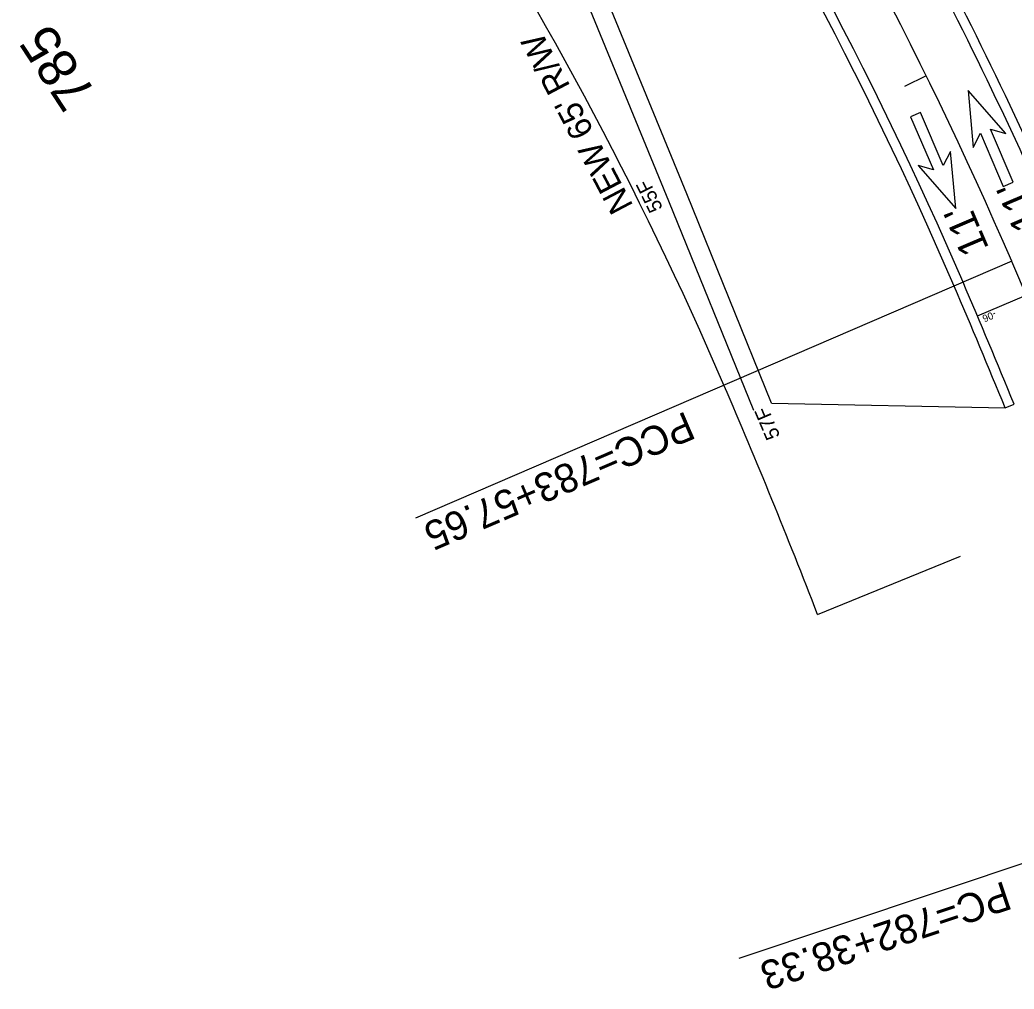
# Model space of a CAD drawing. Extents: x 1551641 to 1624343, y 1119533 to 1136600.
# Drawn here: x 1552695 to 1552901.3, y 1133721.6 to 1133922.6 of the extents above; entities that cross this region are included whole.
import ezdxf

# ---------------------------------------------------------------- set-up
doc = ezdxf.new("R2010")
doc.units = 0
for name, color, linetype in [('RD_HC_Cl', 7, 'Continuous'), ('RD_HC_CL_Rel', 7, 'Continuous'), ('RD_HC_Data', 7, 'Continuous'), ('RD_HC_Data_Tic', 7, 'Continuous'), ('RD_HC_TX_Sta50', 7, 'Continuous'), ('RD_PD_ALT1_TX', 7, 'Continuous'), ('RD_PD_CstnLmt', 7, 'Continuous'), ('RD_PD_CstnLmt_TX', 7, 'Continuous'), ('RD_PD_DR_ErosCtrl', 7, 'Continuous'), ('RD_PD_Final_TrvlWay', 7, 'Continuous'), ('RD_PD_Final_TX', 7, 'Continuous'), ('RD_PD_PaveShd', 7, 'Continuous'), ('RD_PD_RW', 7, 'Continuous')]:
    doc.layers.add(name, color=color, linetype=linetype)

msp = doc.modelspace()

# ---------------------------------------------------------------- linework, layer by layer
at = {"layer": 'RD_HC_Cl'}
msp.add_arc((1551585.14, 1133306.13), 1432.4, 18.5195, 23.29239, dxfattribs=at)
at = {"layer": 'RD_HC_CL_Rel'}
msp.add_arc((1552135.69, 1133543.15), 833, 23.29239, 33.23375, dxfattribs=at)
at = {"layer": 'RD_HC_Data'}
for p, q in [((1552900.8, 1133872.54), (1552777.09, 1133819.28)), ((1552943.36, 1133761.1), (1552844.19, 1133727.88))]:
    msp.add_line(p, q, dxfattribs=at)
at = {"layer": 'RD_HC_Data_Tic'}
msp.add_line((1552883.07, 1133911), (1552878.58, 1133908.79), dxfattribs=at)
at = {"layer": 'RD_PD_ALT1_TX'}
msp.add_line((1552893.68, 1133861.21), (1552903.8, 1133865.5), dxfattribs=at)
at = {"layer": 'RD_PD_CstnLmt'}
for p, q in [((1552833.37, 1133886.53), (1552815.52, 1133930.05)), ((1552850.98, 1133843.1), (1552833.37, 1133886.53)), ((1552850.98, 1133843.1), (1552899.45, 1133842.13))]:
    msp.add_line(p, q, dxfattribs=at)
at = {"layer": 'RD_PD_DR_ErosCtrl'}
for p, q in [((1552829.66, 1133885.02), (1552811.89, 1133928.36)), ((1552847.27, 1133841.59), (1552829.66, 1133885.02))]:
    msp.add_line(p, q, dxfattribs=at)
at = {"layer": 'RD_PD_Final_TrvlWay'}
for centre, radius, start, end in [((1552135.69, 1133543.15), 844, 23.29239, 33.23375), ((1552135.69, 1133543.15), 822, 23.29239, 33.23375), ((1551585.14, 1133306.13), 1421.4, 22.1864, 23.29239)]:
    msp.add_arc(centre, radius, start, end, dxfattribs=at)
at = {"layer": 'RD_PD_Final_TX'}
for p, q in [((1552899.58, 1133899.06), (1552891.78, 1133907.96)), ((1552891.78, 1133907.96), (1552892.82, 1133896.17)), ((1552881.9, 1133903.42), (1552879.83, 1133902.54)), ((1552886.61, 1133892.39), (1552881.9, 1133903.42)), ((1552879.83, 1133902.54), (1552884.55, 1133891.5)), ((1552892.82, 1133896.17), (1552894.34, 1133899.1)), ((1552894.34, 1133899.1), (1552899.06, 1133888.07)), ((1552901.13, 1133888.95), (1552896.41, 1133899.99)), ((1552896.41, 1133899.99), (1552899.58, 1133899.06)), ((1552888.13, 1133895.32), (1552886.61, 1133892.39)), ((1552889.18, 1133883.53), (1552888.13, 1133895.32)), ((1552881.38, 1133892.43), (1552889.18, 1133883.53)), ((1552884.55, 1133891.5), (1552881.38, 1133892.43)), ((1552899.06, 1133888.07), (1552901.13, 1133888.95))]:
    msp.add_line(p, q, dxfattribs=at)
at = {"layer": 'RD_PD_PaveShd'}
msp.add_line((1552899.45, 1133842.13), (1552901.3, 1133842.88), dxfattribs=at)
for centre, radius, start, end in [((1552135.69, 1133543.15), 846, 23.29239, 33.23375), ((1552135.69, 1133543.15), 820, 23.29239, 33.23375), ((1551585.14, 1133306.13), 1419.4, 22.1864, 23.29239)]:
    msp.add_arc(centre, radius, start, end, dxfattribs=at)
at = {"layer": 'RD_PD_RW'}
msp.add_line((1552860.53, 1133799.26), (1552890.16, 1133811.34), dxfattribs=at)
for centre, radius, start, end in [((1552135.69, 1133543.15), 768, 23.29239, 33.23375), ((1551585.14, 1133306.13), 1367.4, 21.13881, 23.29239)]:
    msp.add_arc(centre, radius, start, end, dxfattribs=at)

# ---------------------------------------------------------------- texts
at = {"layer": 'RD_HC_Data'}
for s, rotation, p in [('PCC=783+57.65', 203.2924, (1552833.22, 1133841.52)), ('PC=782+38.33', 198.5195, (1552899.32, 1133744.03))]:
    msp.add_text(s, height=6, rotation=rotation, dxfattribs=at).set_placement(p)
at = {"layer": 'RD_HC_TX_Sta50'}
msp.add_text('785', height=8, rotation=123.2337, dxfattribs=at).set_placement((1552710.99, 1133907.37))
at = {"layer": 'RD_PD_ALT1_TX'}
msp.add_text('-06', height=1.5, rotation=202.9864, dxfattribs=at).set_placement((1552897.22, 1133862.36))
at = {"layer": 'RD_PD_CstnLmt_TX'}
for s, rotation, p in [('55F', 116.2053, (1552828.48, 1133883.58)), ('57F', 112.9864, (1552852.8, 1133836.29))]:
    msp.add_text(s, height=3, rotation=rotation, dxfattribs=at).set_placement(p)
at = {"layer": 'RD_PD_Final_TX'}
for p in [(1552907.08, 1133880.25), (1552896.16, 1133875.26)]:
    msp.add_text("11'", height=6, rotation=113.1378, dxfattribs=at).set_placement(p)
at = {"layer": 'RD_PD_RW'}
msp.add_text("NEW 65' R/W", height=5, rotation=117.7788, dxfattribs=at).set_placement((1552822.35, 1133884.07))

doc.saveas('drawing.dxf')
